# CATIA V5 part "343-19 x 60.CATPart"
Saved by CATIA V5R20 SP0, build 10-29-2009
Part number: 343-19 x 60
Definition: NONE
Nomenclature: 343-19 x 60
Source: Unknown
Description: 343-19 x 60
Bounding box of the stored display mesh (mm): x 0 to 60, y -15 to 15, z -15 to 15
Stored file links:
  C:\Users\Utente\Desktop\IO LAVORO\3D X SITO CF\X SITO\343-348\343-19 x 60.CATPart
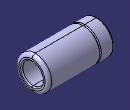
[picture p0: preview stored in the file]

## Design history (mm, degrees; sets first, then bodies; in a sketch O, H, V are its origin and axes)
Body1 "343-19 x 60" (main body)
  Solid1: solid without history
